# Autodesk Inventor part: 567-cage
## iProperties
Author: Administrator
Shininess: 64.0
Angle Display Precision: 2
Document Length Units: 11272
Document Angle Units: 11286
Document Time Units: 11279
Document Mass Units: 11290
Document Length Units Precision: 3
Document Angle Units Precision: 2
Compacted: True
PropertySet Name: _Private Model Information
Created: 2002-03
Part Number: 567-cage
Material: ASTM A36 HRS
Document SubType Name: Modeling
Designer: Administrator
Control State: 0
Master: False
Checked Out: False
PropertySet Name: Design Tracking Control
Density: 0.0
Volumn: 0.0
Area: 0.0
PropertySet Name: Model Information
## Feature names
1. Revolution1
2. Extrusion1
3. Circular Pattern1
